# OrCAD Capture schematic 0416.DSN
size D
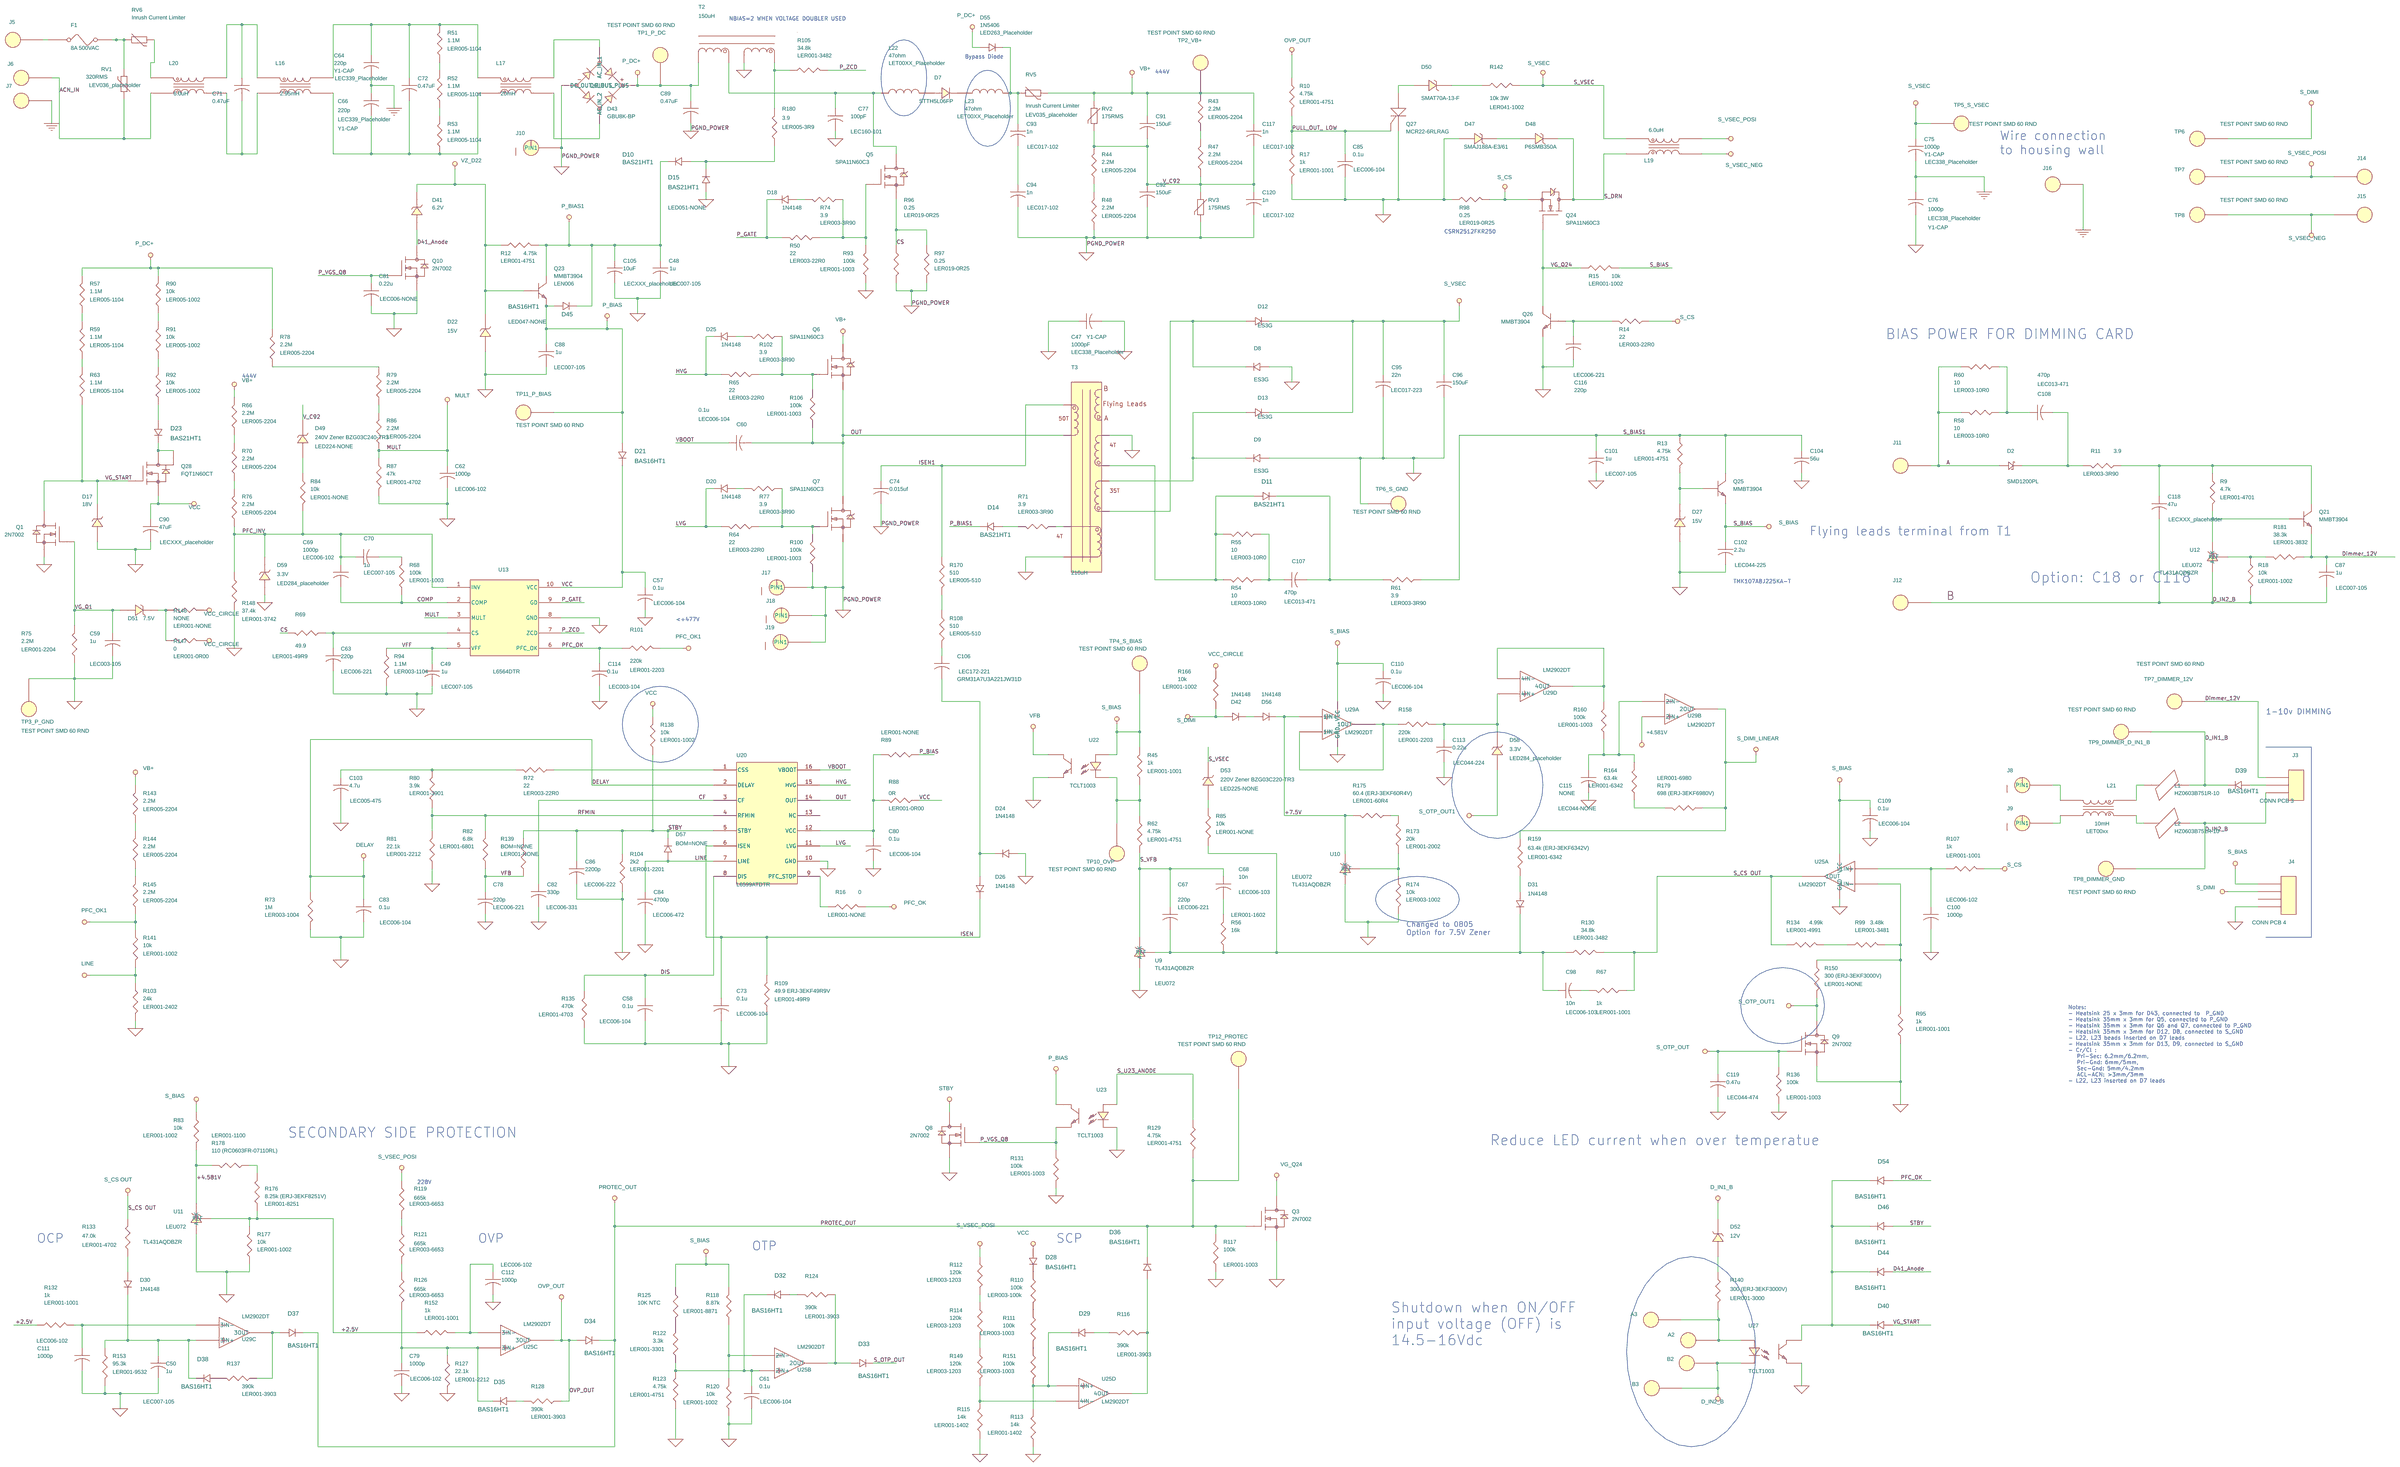
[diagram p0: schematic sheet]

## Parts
A2  TEST POINT SMD 107 RND  [TP-45RD25]
A3  TEST POINT SMD 107 RND  [TP-45RD25]
B2  TEST POINT SMD 107 RND  [TP-45RD25]
B3  TEST POINT SMD 107 RND  [TP-45RD25]
C47  1000pF  [crad-13x4x9p5mm]
C48  1u  [c0805w]
C49  1u  [c0805]
C50  1u  [c0805]
C57  0.1u  [c0603]
C58  0.1u  [c0603w]
C59  1u  [c0603w]
C60  0.1u  [c0603w]
C61  0.1u  [c0603W]
C62  1000p  [c0603W]
C63  220p  [c0603W]
C64  220p  [crad-13x4x9p5mm]
C66  220p  [crad-13x4x9p5mm]
C67  220p  [c0603W]
C68  10n  [c0603W]
C69  1000p  [c0603]
C70  1u  [c0805]
C71  0.47uF  [cap-b32922-9x18mm]
C72  0.47uF  [cap-b32922-9x18mm]
C73  0.1u  [c0603w]
C74  0.015uf  [cap-b32672-18x7x12p5mm]
C75  1000p  [crad-13x4x9p5mm]
C76  1000p  [crad-13x4x9p5mm]
C77  100pF  [c0805]
C78  220p  [c0603w]
C79  1000p  [c0603w]
C80  0.1u  [c0603w]
C81  0.22u  [c0603w]
C82  330p  [c0603w]
C83  0.1u  [c0603w]
C84  4700p  [c0603w]
C85  0.1u  [c0603w]
C86  2200p  [c0603]
C87  1u  [c0805w]
C88  1u  [c0805w]
C89  0.47uF  [cap-ecwf-20p5x13p5-17p5]
C90  47uF  [crad-6p3odx11l]
C91  150uF  [CRAD-18odx25l]
C92  150uF  [CRAD-18odx25l]
C93  1n  [c1206]
C94  1n  [c1206]
C95  22n  [c1206]
C96  150uF  [CRAD-18odx25l]
C98  10n  [c0603W]
C100  1000p  [c0603w]
C101  1u  [c0805w]
C102  2.2u  [c0805]
C103  4.7u  [c1206]
C104  56u  [crad-6p3odx11l]
C105  10uF  [crad-6p3odx11l]
C106  GRM31A7U3A221JW31D  [c1206]
C107  470p  [c0805w]
C108  470p  [c0805w]
C109  0.1u  [c0603W]
C110  0.1u  [c0603W]
C111  1000p  [c0603W]
C112  1000p  [c0603W]
C113  0.22u  [c0805w]
C114  0.1u  [c0603]
C115  NONE  [c0805w]
C116  220p  [c0603w]
C117  1n  [c1206]
C118  47u  [crad-6p3odx11l]
C119  0.47u  [c0805w]
C120  1n  [c1206]
D2  SMD1200PL  [DIO-SOD123]
D7  STTH5L06FP  [DIO-STTH5L06FP]
D8  ES3G  [dio-smc]
D9  ES3G  [dio-smc]
D10  BAS21HT1  [SOD323w]
D11  BAS21HT1  [SOD323w]
D12  ES3G  [dio-smc]
D13  ES3G  [dio-smc]
D14  BAS21HT1  [SOD323w]
D15  BAS21HT1  [SOD323w]
D17  18V  [SOD123]
D18  1N4148  [SOD323]
D20  1N4148  [SOD323w]
D21  BAS16HT1  [SOD323w]
D22  15V  [SOD323w]
D23  BAS21HT1  [SOD323w]
D24  1N4148  [SOD323w]
D25  1N4148  [SOD323w]
D26  1N4148  [SOD323w]
D27  15V  [SOD323]
D28  BAS16HT1  [SOD323w]
D29  BAS16HT1  [SOD323w]
D30  1N4148  [SOD323w]
D31  1N4148  [SOD323]
D32  BAS16HT1  [SOD323w]
D33  BAS16HT1  [SOD323w]
D34  BAS16HT1  [SOD323]
D35  BAS16HT1  [SOD323w]
D36  BAS16HT1  [SOD323w]
D37  BAS16HT1  [SOD323]
D38  BAS16HT1  [SOD323]
D39  BAS16HT1  [SOD323w]
D40  BAS16HT1  [SOD323w]
D41  6.2V  [SOD123]
D42  1N4148  [SOD323w]
D43  GBU8K-BP  [bridge-GBU8X]
D44  BAS16HT1  [SOD323w]
D45  BAS16HT1  [SOD323w]
D46  BAS16HT1  [SOD323w]
D47  SMAJ188A-E3/61  [dio-sma]
D48  P6SMB350A  [dio-smb]
D49  240V Zener BZG03C240-TR3  [dio-smb]
D50  SMAT70A-13-F  [dio-sma]
D51  7.5V  [SOD123]
D52  12V  [SOD323w]
D53  220V Zener BZG03C220-TR3  [dio-smb]
D54  BAS16HT1  [SOD323w]
D55  1N5406  [DIO-DO-201AD]
D56  1N4148  [SOD323w]
D57  BOM=NONE  [SOD323w]
D58  3.3V  [SOD123]
D59  3.3V  [SOD123]
F1  8A 500VAC  [FUSE-0477-V_5A]
J3  CONN PCB 3  [conn3-100]
J4  CONN PCB 4  [conn4-100]
J5  TEST POINT SMD 107 RND  [tp-107rd87]
J6  TEST POINT SMD 107 RND  [tp-107rd87]
J7  TEST POINT SMD 107 RND  [tp-107rd87]
J8  22_AWG  [TP-107RD87]
J9  22_AWG  [TP-107RD87]
J10  18_AWG  [TP-95ob75pth]
J11  TEST POINT SMD 30 RND  [tp-45rd25]
J12  TEST POINT SMD 30 RND  [tp-45rd25]
J14  TEST POINT SMD 107 RND  [tp-107rd87]
J15  TEST POINT SMD 107 RND  [tp-107rd87]
J16  TEST POINT SMD 107 RND  [tp-107rd87]
J17  18_AWG  [TP-95ob75pth]
J18  18_AWG  [TP-95ob75pth]
J19  18_AWG  [TP-95ob75pth]
L1  HZ0603B751R-10  [fb0603w]
L2  HZ0603B751R-10  [fb0603w]
L16  2.95mH  [IND-LET0121-21p3x13p5]
L17  20mH  [IND-LET0120-29x15]
L19  6.0uH  [ind-let0163]
L20  6.0uH  [ind-lc9]
L21  10mH  [ind-ee8-3p4m1]
L22  47ohm  [f0805]
L23  47ohm  [f0805]
Q1  2N7002  [sot23_3-12]
Q3  2N7002  [sot23_3-12]
Q5  SPA11N60C3  [to220-3]
Q6  SPA11N60C3  [to220-3]
Q7  SPA11N60C3  [to220-3]
Q8  2N7002  [sot23_3-12]
Q9  2N7002  [sot23_3-12]
Q10  2N7002  [sot23_3-12]
Q21  MMBT3904  [SOT23_1-32]
Q23  MMBT3904  [SOT23_1-32]
Q24  SPA11N60C3  [to220-3]
Q25  MMBT3904  [SOT23_1-32]
Q26  MMBT3904  [SOT23_1-32]
Q27  MCR22-6RLRAG  [TO-92-KGA]
Q28  FQT1N60CT  [sot223-4]
R9  4.7k  [r0603]
R10  4.75k  [r0603w]
R11  3.9  [r0805w]
R12  4.75k  [r0603w]
R13  4.75k  [r0603]
R14  22  [r0805w]
R15  10k  [r0603w]
R16  0  [r0603w]
R17  1k  [r0603w]
R18  10k  [r0603w]
R43  2.2M  [r1206]
R44  2.2M  [r1206]
R45  1k  [r0603w]
R47  2.2M  [r1206]
R48  2.2M  [r1206]
R50  22  [r0805]
R51  1.1M  [r1206]
R52  1.1M  [r1206]
R53  1.1M  [r1206]
R54  10  [r0805w]
R55  10  [r0805w]
R56  16k  [r0603w]
R57  1.1M  [r1206]
R58  10  [r0805w]
R59  1.1M  [r1206]
R60  10  [r0805w]
R61  3.9  [r0805w]
R62  4.75k  [r0603w]
R63  1.1M  [r1206]
R64  22  [r0805w]
R65  22  [r0805w]
R66  2.2M  [r1206]
R67  1k  [r0603w]
R68  100k  [r0603]
R69  49.9  [r0603]
R70  2.2M  [r1206]
R71  3.9  [r0805w]
R72  22  [r0805w]
R73  1M  [r0805w]
R74  3.9  [r0805]
R75  2.2M  [r0603w]
R76  2.2M  [r1206]
R77  3.9  [r0805w]
R78  2.2M  [r1206]
R79  2.2M  [r1206]
R80  3.9k  [r0603w]
R81  22.1k  [r0603w]
R82  6.8k  [r0603w]
R83  10k  [r0603]
R84  10k  [r0603w]
R85  10k  [r0603]
R86  2.2M  [r1206]
R87  47k  [r0603]
R88  0R  [r0603]
R89  0  [r0603]
R90  10k  [r1206]
R91  10k  [r1206]
R92  10k  [r1206]
R93  100k  [r0603]
R94  1.1M  [r0805]
R95  1k  [r0603w]
R96  0.25  [r2512]
R97  0.25  [r2512]
R98  0.25  [r2512]
R99  3.48k  [r0603]
R100  100k  [r0603w]
R101  220k  [r0603]
R102  3.9  [r0805w]
R103  24k  [r0603w]
R104  2k2  [r0603w]
R105  34.8k  [r0603w]
R106  100k  [r0603w]
R107  1k  [r0603w]
R108  510  [r1206]
R109  49.9 ERJ-3EKF49R9V  [r0603w]
R110  100k  [r0805w]
R111  100k  [r0805w]
R112  120k  [r0805w]
R113  14k  [r0603w]
R114  120k  [r0805w]
R115  14k  [r0603]
R116  390k  [r0603]
R117  100k  [r0603w]
R118  8.87k  [r0603]
R119  665k  [r0805w]
R120  10k  [r0603]
R121  665k  [r0805w]
R122  3.3k  [r0603]
R123  4.75k  [r0603w]
R124  390k  [r0603w]
R125  10K NTC  [r0603]
R126  665k  [r0805w]
R127  22.1k  [r0603w]
R128  390k  [r0603w]
R129  4.75k  [r0603w]
R130  34.8k  [r0603w]
R131  100k  [r0603w]
R132  1k  [r0603]
R133  47.0k  [r0603w]
R134  4.99k  [r0603]
R135  470k  [r0603w]
R136  100k  [r0603w]
R137  390k  [r0603]
R138  10k  [r0603]
R139  BOM=NONE  [r0603w]
R140  300 (ERJ-3EKF3000V)  [r0603]
R141  10k  [r0603w]
R142  10k 3W  [rax-erg-3w-h]
R143  2.2M  [r1206]
R144  2.2M  [r1206]
R145  2.2M  [r1206]
R146  NONE  [r0603w]
R147  0  [r0603w]
R148  37.4k  [r0603w]
R149  120k  [r0805w]
R150  300 (ERJ-3EKF3000V)  [r0603w]
R151  100k  [r0805w]
R152  1k  [r0603w]
R153  95.3k  [r0603]
R158  220k  [r0603w]
R159  63.4k (ERJ-3EKF6342V)  [r0603]
R160  100k  [r0603w]
R164  63.4k  [r0603w]
R166  10k  [r0603w]
R170  510  [r1206]
R173  20k  [r0603w]
R174  10k  [r0805w]
R175  60.4 (ERJ-3EKF60R4V)  [r0603w]
R176  8.25k (ERJ-3EKF8251V)  [r0603w]
R177  10k  [r0603w]
R178  110 (RC0603FR-07110RL)  [r0603w]
R179  698 (ERJ-3EKF6980V)  [r0603w]
R180  3.9  [r1206]
R181  38.3k  [r0603w]
RV1  320RMS  [var-s22k320]
RV2  175RMS  [var-7mm_TVR_S07]
RV3  175RMS  [var-7mm_TVR_S07]
RV5  Inrush Current Limiter  [var-7p5-b57238s]
RV6  Inrush Current Limiter  [var-7p5-b57238s]
T2  150uH  [xfmr-pq32-25_LEX0048_key4-C]
T3  210uH  [XFMR-TXFA-12PIN-c]
TP1_P_DC  TEST POINT SMD 60 RND  [tps-60rd]
TP2_VB+  TEST POINT SMD 60 RND  [tps-60rd]
TP3_P_GND  TEST POINT SMD 60 RND  [tps-60rd]
TP4_S_BIAS  TEST POINT SMD 60 RND  [tps-60rd]
TP5_S_VSEC  TEST POINT SMD 60 RND  [tps-60rd]
TP6  TEST POINT SMD 60 RND  [tps-60rd]
TP6_S_GND  TEST POINT SMD 60 RND  [tps-60rd]
TP7  TEST POINT SMD 60 RND  [tps-60rd]
TP7_DIMMER_12V  TEST POINT SMD 60 RND  [tps-60rd]
TP8  TEST POINT SMD 60 RND  [tps-60rd]
TP8_DIMMER_GND  TEST POINT SMD 60 RND  [tps-60rd]
TP9_DIMMER_D_IN1_B  TEST POINT SMD 60 RND  [tps-60rd]
TP10_OVP  TEST POINT SMD 60 RND  [tps-60rd]
TP11_P_BIAS  TEST POINT SMD 60 RND  [tps-60rd]
TP12_PROTEC  TEST POINT SMD 60 RND  [tps-60rd]
U9  TL431AQDBZR  [SOT23_1-32]
U10  TL431AQDBZR  [SOT23_1-32]
U11  TL431AQDBZR  [SOT23_1-32]
U12  TL431AQDBZR  [SOT23_1-32]
U13  L6564DTR  [sso-10]
U20  L6599ATDTR  [so-16]
U22  TCLT1003  [opto-sop-4l]
U23  TCLT1003  [opto-sop-4l]
U25  LM2902DT  [so-14]  (sections A,B,C,D)
U27  TCLT1003  [opto-sop-4l]
U29  LM2902DT  [so-14]  (sections A,B,C,D)

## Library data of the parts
A2 A3 B2 B3 J5-J7 J14-J16 = TEST_POINT_SMD_107_RND
C47 = LEC039_Y_1000PF_10MM: LLF Part Number: LEC338_Placeholder; TYPE: Y1-CAP
C48-C50 C70 C87 C88 C101 = LEC007_0805_50V: LLF Part Number: LEC007-105
C57 C58 C60 C61 C73 C80 C83 C85 C109 C110 = LEC006_0603_50V: LLF Part Number: LEC006-104
C59 = LEC006_0603_50V: LLF Part Number: LEC003-105
C62 C69 C79 C100 C111 C112 = LEC006_0603_50V: LLF Part Number: LEC006-102
C63 C67 C78 C116 = LEC006_0603_50V: LLF Part Number: LEC006-221
C64 C66 = LEC040_Y_4700PF_10MM: LLF Part Number: LEC339_Placeholder; TYPE: Y1-CAP
C68 C98 = LEC006_0603_50V: LLF Part Number: LEC006-103
C71 C72 = LEC256_FILM_0.47uF_310V
C74 = LEC330_FILM_0.015uF_1.6KVDC_Rad
C75 C76 = LEC040_Y_4700PF_10MM: LLF Part Number: LEC338_Placeholder; TYPE: Y1-CAP
C77 = LEC160_NPO_0805_1000V: LLF Part Number: LEC160-101
C81 = LEC006_0603_50V: LLF Part Number: LEC006-NONE
C82 = LEC006_0603_50V: LLF Part Number: LEC006-331
C84 = LEC006_0603_50V: LLF Part Number: LEC006-472
C86 = LEC006_0603_50V: LLF Part Number: LEC006-222
C89 = LEC255_FILM_0.47uF_630V
C90 C105 C118 = LEC121_CAP_AL_56UF_35V: LLF Part Number: LECXXX_placeholder
C91 C92 C96 = LEC249_AL_150UF_250V_18odx25
C93 C94 C117 C120 = LEC017_1206_500V: LLF Part Number: LEC017-102
C95 = LEC017_1206_500V: LLF Part Number: LEC017-223
C102 = LEC044_0805_25V: LLF Part Number: LEC044-225
C103 = LEC005_1206_16V: LLF Part Number: LEC005-475
C104 = LEC121_CAP_AL_56UF_35V
C106 = LEC172_X7R_1206_1000V: LLF Part Number: LEC172-221
C107 C108 = LEC013_0805_200V: LLF Part Number: LEC013-471
C113 = LEC044_0805_25V: LLF Part Number: LEC044-224
C114 = LEC003_0603_16V: LLF Part Number: LEC003-104
C115 = LEC044_0805_25V: LLF Part Number: LEC044-NONE
C119 = LEC044_0805_25V: LLF Part Number: LEC044-474
D2 = LED166_S_200V_1A_SOD123
D7 = LED181_600V_5V_UF_TO220
D8 D9 D12 D13 = LED066_400V_3A_ES3G_SMC
D10 D11 D14 D23 = LED051_BAS21HT1_SOD323
D15 = LED051_BAS21HT1_SOD323: LLF Part Number: LED051-NONE
D17 = LED184_Z_18V_500mW_SOD123
D18 D20 D24-D26 D30 D31 D42 D56 D57 = LED002_1N4148_SOD323
D21 D28 D29 D32-D40 D44 D46 D54 = LED047_BAS16HT1_SOD323
D22 D27 = LED022_Z_15V_SOD323
D41 = LED190_Z_6.2V_500mW_SOD123
D43 = LED182_BRIDGE_800V_8A_GBU8K
D45 = LED047_BAS16HT1_SOD323: LLF Part Number: LED047-NONE
D47 = LED187_TVS_188V_300W_SMA
D48 = LED188_TVS_350V_600W_SMB
D49 = LED188_TVS_350V_600W_SMB: LLF Part Number: LED224-NONE
D50 = LED183_TVS_70V_400W_SMA
D51 = LED185_Z_7.5V_500mW_SOD123
D52 = LED012_Z_12V_SOD323
D53 = LED188_TVS_350V_600W_SMB: LLF Part Number: LED225-NONE
D55 = LED128_200V_3A_DO-201AD: ALT_SYMBOLS: DIO-DO-201AD-V; LLF Part Number: LED263_Placeholder
D58 D59 = LED185_Z_7.5V_500mW_SOD123: LLF Part Number: LED284_placeholder
F1 = LEF034_8A_500V_0477_TH
J3 = CONN_PCB_3
J4 = CONN_PCB_4
J8 J9 = 22_AWG
J10 J17-J19 = 18_AWG
J11 J12 = TEST_POINT_SMD_30_RND
L1 L2 = LET0011_FERRITE_0603_200MA
L16 = LET0121_CM_2.95mH_21.3x13.5mm
L17 = LET0120_CM_20mH_29x15mm
L19 = LET0163_CM_LC9-752
L20 = LET0081_CM_LC9-671
L21 = LET0029_CM_1.0MH_EE8-3P4M1-0-00: LLF Part Number: LET00xx
L22 L23 = LET0030_IND_SMT_BK2125HS470-T: LLF Part Number: LET00XX_Placeholder
Q1 Q3 Q8-Q10 = LEN008_FET_N_60V_2N7002_SOT23
Q5-Q7 Q24 = LEN128_FET_N_650V_11A_TO220
Q21 Q25 Q26 = LEN006_NPN_40V_MMBT3904_SOT23
Q23 = LEN006_NPN_40V_MMBT3904_SOT23: LLF Part Number: LEN006
Q27 = LEN132_THYRIS_400V_1.5A_TO-92
Q28 = LEN183_FET_SOT223
R9 = LER001_0603_1: LLF Part Number: LER001-4701
R10 R12 R13 R62 R123 R129 = LER001_0603_1: LLF Part Number: LER001-4751
R11 R61 R71 R74 R77 R102 = LER003_0805_1: LLF Part Number: LER003-3R90
R14 R50 R64 R65 R72 = LER003_0805_1: LLF Part Number: LER003-22R0
R15 R18 R83 R120 R138 R141 R166 R177 = LER001_0603_1: LLF Part Number: LER001-1002
R16 R84 R85 R89 R139 R146 R150 = LER001_0603_1: LLF Part Number: LER001-NONE
R17 R45 R67 R95 R107 R132 R152 = LER001_0603_1: LLF Part Number: LER001-1001
R43 R44 R47 R48 R66 R70 R76 R78 R79 R86 R143-R145 = LER005_1206_1: LLF Part Number: LER005-2204
R51-R53 R57 R59 R63 = LER005_1206_1: LLF Part Number: LER005-1104
R54 R55 R58 R60 = LER003_0805_1: LLF Part Number: LER003-10R0
R56 = LER001_0603_1: LLF Part Number: LER001-1602
R68 R93 R100 R106 R117 R131 R136 R160 = LER001_0603_1: LLF Part Number: LER001-1003
R69 R109 = LER001_0603_1: LLF Part Number: LER001-49R9
R73 = LER003_0805_1: LLF Part Number: LER003-1004
R75 = LER001_0603_1: LLF Part Number: LER001-2204
R80 = LER001_0603_1: LLF Part Number: LER001-3901
R81 R127 = LER001_0603_1: LLF Part Number: LER001-2212
R82 = LER001_0603_1: LLF Part Number: LER001-6801
R87 R133 = LER001_0603_1: LLF Part Number: LER001-4702
R88 R147 = LER001_0603_1: LLF Part Number: LER001-0R00
R90-R92 = LER005_1206_1: LLF Part Number: LER005-1002
R94 = LER003_0805_1: LLF Part Number: LER003-1104
R96-R98 = LER019_2512_1: LLF Part Number: LER019-0R25
R99 = LER001_0603_1: LLF Part Number: LER001-3481
R101 R158 = LER001_0603_1: LLF Part Number: LER001-2203
R103 = LER001_0603_1: LLF Part Number: LER001-2402
R104 = LER001_0603_1: LLF Part Number: LER001-2201
R105 R130 = LER001_0603_1: LLF Part Number: LER001-3482
R108 R170 = LER005_1206_1: LLF Part Number: LER005-510
R110 = LER003_0805_1: LLF Part Number: LER003-100k
R111 R151 = LER003_0805_1: LLF Part Number: LER003-1003
R112 R114 R149 = LER003_0805_1: LLF Part Number: LER003-1203
R113 R115 = LER001_0603_1: LLF Part Number: LER001-1402
R116 R124 R128 R137 = LER001_0603_1: LLF Part Number: LER001-3903
R118 = LER001_0603_1: LLF Part Number: LER001-8871
R119 R121 R126 = LER003_0805_1: LLF Part Number: LER003-6653
R122 = LER001_0603_1: LLF Part Number: LER001-3301
R125 = LER024_THERMISTOR_10K_0603
R134 = LER001_0603_1: LLF Part Number: LER001-4991
R135 = LER001_0603_1: LLF Part Number: LER001-4703
R140 = LER001_0603_1: LLF Part Number: LER001-3000
R142 = LER041_3W_AX_TH_5: LLF Part Number: LER041-1002
R148 = LER001_0603_1: LLF Part Number: LER001-3742
R153 = LER001_0603_1: LLF Part Number: LER001-9532
R159 R164 = LER001_0603_1: LLF Part Number: LER001-6342
R173 = LER001_0603_1: LLF Part Number: LER001-2002
R174 = LER003_0805_1: LLF Part Number: LER003-1002
R175 = LER001_0603_1: LLF Part Number: LER001-60R4
R176 = LER001_0603_1: LLF Part Number: LER001-8251
R178 = LER001_0603_1: LLF Part Number: LER001-1100
R179 = LER001_0603_1: LLF Part Number: LER001-6980
R180 = LER005_1206_1: LLF Part Number: LER005-3R9
R181 = LER001_0603_1: LLF Part Number: LER001-3832
RV1 = LEV026_14MM_S14K320E2_320RMS: LLF Part Number: LEV036_placeholder
RV2 RV3 = LEV028_7MM_TVR07271_175RMS
RV5 = LEV035_b572238S_7p5mm: LLF Part Number: LEV035_placeholder
RV6 = LEV035_b572238S_7p5mm
T2 = LEX0048_XFRM_PQ3225_300uH: ALT_SYMBOLS: XFMR-PQ32-25_lex0048_key4
T3 = LEX0065_XFRM_ETD-34-H-12P
TP1_P_DC TP2_VB+ TP3_P_GND TP4_S_BIAS TP5_S_VSEC TP6 TP6_S_GND TP7 TP7_DIMMER_12V TP8 TP8_DIMMER_GND TP9_DIMMER_D_IN1_B TP10_OVP TP11_P_BIAS TP12_PROTEC = TEST_POINT_SMD_60_RND
U9-U12 = LEU094_ZTL431AFTA_SOT23: LLF Part Number: LEU072
U13 = LEU078_L6564
U20 = LEU168_L6599ATDTR_SO16
U22 U23 U27 = LEU169_TCLT1003_SOP-4L
U25 U29 = LEU172_LM2902DT_SO14

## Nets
+2.5V: R132.2 R152.2 R176.2 R177.1 U11.2(REF)
+4.581V: R83.2 R178.1 U11.3(K) U29.5(2IN+)
+7.5V: D56.K(2) R175.1 U10.3(K) U29.3(1IN+)
GND_SIGNAL: C47.2 C50.2 C61.2 C76.2 C79.2 C85.2 C95.2 C96.2 C100.2 C101.2 C102.2 C104.2 C109.2 C110.2 C111.2 C112.2 C113.2 C115.2 C116.2 C119.2 D8.A(1) D9.A(1) D27.A(ANODE) D47.A(1) J4.4 Q3.2(SOURCE) Q9.2(SOURCE) Q26.2(E) Q27.K R17.1 R95.2 R98.1 R113.2 R115.2 R117.2 R120.2 R123.2 R127.2 R136.2 R153.2 R174.1 R177.2 T3.6 TP6_S_GND.1 U9.1(A) U10.1(A) U11.1(A) U23.2 U25.11(GND) U29.11(GND)
PGND_SIGNAL: C47.1 C48.2 C49.2 C57.2 C58.2 C59.2 C62.2 C63.2 C73.2 C74.2 C77.2 C78.2 C80.2 C81.2 C82.2 C83.2 C84.2 C86.2 C88.2 C89.2 C90.2 C92.2 C94.2 C103.2 C105.2 C114.2 C120.2 D15.A(1) D17.A(ANODE) D22.A(ANODE) D24.A(1) D43.4(DC_OUT_MINUS) D59.A(ANODE) J10.1(PIN1) J17.1(PIN1) J18.1(PIN1) J19.1(PIN1) Q1.2(SOURCE) Q7.3(S) Q8.2(SOURCE) Q10.2(SOURCE) R48.1 R73.1 R75.2 R81.2 R87.2 R93.2 R94.1 R96.2 R97.2 R100.2 R103.2 R104.2 R109.2 R131.1 R135.2 R148.2 RV3.2 T2.2 T3.12 TP3_P_GND.1 U13.8(GND) U20.10(GND) U22.3 U27.3
VCC: C57.1 C90.1 D21.K(2) Q28.3(SOURCE) R88.2 R138.1 U13.10(VCC)
A: D2.A(1) J11.1 R58.1 R60.1
ACN_IN: J6.1 L20.3 RV1.1
CF: C82.1 U20.3(CF)
COMP: C69.2 R68.1 U13.2(COMP)
CS: Q5.3(S) R69.1 R96.1 R97.1
D41_Anode: D41.A(ANODE) D44.A(1) Q10.3(DRAIN)
D_IN1_B: D39.K(2) D52.K(CATHODE) L1.2 TP9_DIMMER_D_IN1_B.1
D_IN2_B: B2.1 B3.1 C87.2 C118.2 J3.3 J12.1 L2.2 R18.1 TP8_DIMMER_GND.1 U12.1(A) U27.2
DELAY: C83.1 R73.2 U20.2(DELAY)
Dimmer_12V: C87.1 J3.1 Q21.2(E) R181.2 TP7_DIMMER_12V.1
DIS: C58.1 R135.1 U20.8(DIS)
HVG: D25.K(2) R65.1 U20.15(HVG)
ISEN: C73.1 D26.K(2) R109.1 U20.6(ISEN)
ISEN1: C74.1 R170.1 T3.7
LINE: C84.1 D57.A(1) R103.1 R141.2 U20.7(LINE)
LVG: D20.K(2) R64.1 U20.11(LVG)
MULT: C62.1 R86.1 R87.1 U13.3(MULT)
OUT: C60.2 Q6.3(S) Q7.2(D) R106.2 T3.9 U20.14(OUT)
OVP_OUT: D34.A(1) R10.2 R128.2 U25.8(3OUT)
P_BIAS: C88.1 D21.A(1) D45.A(1) Q23.2(E) R89.2 R146.2 TP11_P_BIAS.1 U23.4
P_BIAS1: C48.1 C105.1 D10.K(2) D14.K(2) D45.K(2) Q23.1(C) R12.1 R147.2
P_DC+: C89.1 D43.1(DC_OUT_PLUS) D55.A(1) R57.2 R78.2 R90.2 T2.10 TP1_P_DC.1
P_EGND2: C64.2 C66.1 J7.1
P_GATE: D18.K(2) R50.1 U13.9(GD)
P_VGS_Q8: C81.1 Q8.1(GATE) Q10.1(GATE) R131.2 U23.3
P_ZCD: R105.2 U13.7(ZCD)
PFC_INV: C69.1 C70.1 D59.K(CATHODE) R76.1 R84.2 R148.1 U13.1(INV)
PFC_OK: C114.1 D54.A(1) R16.1 R101.1 U13.6(PFC_OK)
PFC_OK1: R101.2 R141.1 R145.1
PROTEC_OUT: D34.K(2) D36.K(2) D37.K(2) Q3.1(GATE) R117.1 R129.1 TP12_PROTEC.1
PULL_OUT_ LOW: C85.1 Q27.G R10.1 R17.2
RFMIN: R80.2 R81.1 R82.1 U20.4(RFMIN)
S_BIAS: C102.1 C109.1 C110.1 J4.1 Q25.2(E) R15.1 R45.2 R83.1 R118.1 R125.1 R166.1 TP4_S_BIAS.1 U22.1 U25.4(VCC) U29.4(VCC)
S_BIAS1: C101.1 C104.1 Q25.1(C) R13.2 R61.2
S_CS: Q24.3(S) R14.2 R98.2 R107.1
S_CS OUT: R67.1 R130.1 R133.1 R134.2 U25.1(1OUT)
S_DIMI: D42.A(1) J4.2 R166.2 TP6.1
S_DIMI_LINEAR: R159.1 R179.2 U29.7(2OUT)
S_DRN: D28.A(1) D48.K(2) L19.1 Q24.2(D)
S_EGND: C75.2 C76.1 J16.1
S_OTP_OUT: C119.1 D33.K(2) Q9.1(GATE) R136.1
S_OTP_OUT1: D58.A(ANODE) Q9.3(DRAIN) R150.2
S_U23_ANODE: R129.2 U23.1
S_VFB: C67.1 C68.1 R62.1 U9.3(K)
S_VSEC: C75.1 C95.1 C96.1 D12.K(2) D13.K(2) D53.K(2) L19.2 R142.2 TP5_S_VSEC.1
S_VSEC_NEG: J15.1 L19.4 TP8.1
S_VSEC_POSI: J14.1 L19.3 R112.2 R119.2 TP7.1
STBY: C86.1 D46.A(1) D57.K(2) Q8.3(DRAIN) R104.1 R138.2 R139.1 U20.5(STBY)
V_C92: C91.2 C92.1 C117.2 C120.1 D49.K(2) R44.2 R47.1 RV2.2 RV3.1
VB+: C91.1 C117.1 Q6.2(D) R43.2 R66.2 R143.2 RV2.1 RV5.2 TP2_VB+.1
VBOOT: C60.1 U20.16(VBOOT)
VFB: C78.1 R82.2 R139.2 U22.4
VFF: C49.1 R94.2 U13.5(VFF)
VG_Q1: C59.1 D51.A(ANODE) Q1.1(GATE) R75.1
VG_Q24: Q3.3(DRAIN) Q24.1(G) Q26.1(C) R15.2
VG_START: D17.K(CATHODE) D40.A(1) Q1.3(DRAIN) Q28.1(GATE) R63.1
Vz_D22: D22.K(CATHODE) D41.K(CATHODE) Q23.3(B) R12.2
N10685235: C67.2 C98.1 D31.K(2) R56.1 R85.2 R130.2 U9.2(REF)
N10791701: D43.3(AC_IN_2) L17.4
N11619138: D11.A(1) R54.1 R55.1 T3.5
N12455128: C118.1 Q21.1(C) R9.2 R11.1
N12455191: Q21.3(B) R9.1 U12.3(K)
N12479252: C66.2 C72.2 L16.6 L17.1 R53.1
N12482492: D43.2(AC_IN_1) L17.3
N12483638: C64.1 C72.1 L16.4 L17.2 R51.2
N12486998: R91.1 R92.2
N12492728: C77.1 L22.1 Q5.2(D) T2.7
N12498460: C63.1 R69.2 U13.4(CS)
N12508817: C70.2 R68.2
N12511276: Q5.1(G) R50.2 R74.2 R93.1
N12528990: D18.A(1) R74.1
N12530234: D51.K(CATHODE) R146.1 R147.1
N12548888: C108.2 D2.K(2) R11.2
N12549930: D27.K(CATHODE) Q25.3(B) R13.1
N12552720: Q7.1(G) R64.2 R77.2 R100.1
N12552824: D20.A(1) R77.1
N12553598: Q6.1(G) R65.2 R102.2 R106.1
N12553690: D25.A(1) R102.1
N12560183: D8.K(2) D12.A(1) T3.1
N12560208: D9.K(2) D13.A(1) T3.3
N12563637: C106.1 R108.2
N12564955: R115.1 R149.1 U25.13(4IN-)
N12565313: D29.K(2) R113.1 R151.1 U25.12(4IN+)
N12566314: D36.A(1) R116.2 U25.14(4OUT)
N12566402: D29.A(1) R116.1
N12568198: C61.1 D32.K(2) R122.2 R123.1 U25.5(2IN+)
N12568286: R118.2 R120.1 U25.6(2IN-)
N12568438: D33.A(1) R124.2 U25.7(2OUT)
N12568446: D32.A(1) R124.1
N12572856: C79.1 D35.K(2) R126.1 R127.1 U25.10(3IN+)
N12577697: C80.1 R88.1 R89.1 U20.12(VCC)
N12578837: R72.2 U20.1(CSS)
N12578926: C103.1 R72.1 R80.1
N12580845: R45.1 R62.2 TP10_OVP.1 U22.2
N12588270: D37.A(1) R137.2 U29.8(3OUT)
N12589414: C111.1 R132.1 U29.9(3IN-)
N12589934: C50.1 D30.K(2) D38.K(2) R153.1 U29.10(3IN+)
N12590488: R99.2 R134.1
N12595548: R16.2 U20.9(PFC_STOP)
N12630039: C116.1 Q26.3(B) R14.1
N12638686: C107.2 D11.K(2) R61.1
N12638764: C107.1 R54.2 R55.2
N12639429: C108.1 R58.2 R60.2
N12643014: F1.2 RV1.2 RV6.1
N12692273: C106.2 D24.K(2) D26.A(1)
N12699371: R95.1 R99.1 R150.1 U25.2(1IN-)
N12700568: C100.1 R107.2 U25.3(1IN+)
N12707197: C112.1 R152.1 U25.9(3IN-)
N12730169: D30.A(1) R133.2
N12742487: D50.K(2) R142.1
N12743434: D50.A(1) Q27.A
N12747847: D47.K(2) D48.A(1)
N12805428: R158.2 U29.1(1OUT) U29.2(1IN-)
N12808606: D31.A(1) R159.2
N12811049: C113.1 D58.K(CATHODE) R158.1 U29.12(4IN+)
N12832400: R160.1 U29.13(4IN-) U29.14(4OUT)
N12835772: C115.1 R160.2 R164.1 U29.6(2IN-)
N12891714: R108.1 R170.2
N12894362: C68.2 R56.2
N12899357: R173.2 R174.2 U10.2(REF)
N12902064: R173.1 R175.2
N12904550: R176.1 R178.2
N12907390: R164.2 R179.1
N12914336: J8.1(PIN1) L21.3
N12914343: J9.1(PIN1) L21.2
N12914350: L1.1 L21.4
N12914357: L2.1 L21.1
N12914556: D39.A(1) J3.2
N12925506: D49.A(1) R84.1
N12926206: D53.A(1) R85.1
N12934444: R78.1 R79.2
N12960089: D35.A(1) R128.1
N12964640: A2.1 A3.1 R140.2 U27.1
N12966775: D40.K(2) D44.K(2) D46.K(2) D54.K(2) U27.4
N12982559: D52.A(ANODE) R140.1
N13002970: R105.1 R180.2 T2.1
N13004286: D10.A(1) D15.K(2) R180.1
N13021904: C93.1 D55.K(2) L23.2 RV5.1
N13035527: R70.1 R76.2
N13035915: R144.1 R145.2
N13036788: R59.1 R63.2
N13038410: R79.1 R86.2
N13066955: D42.K(2) D56.A(1)
N13100840: D14.A(1) R71.1
N13102481: R71.2 T3.11
N13181221: C98.2 R67.2
N13188239: C93.2 C94.1
N13223633: D23.A(1) R92.1
N13223645: D23.K(2) Q28.2(DRAIN) Q28.4(DRAIN2)
N13277573: R18.2 R181.1 U12.2(REF)
N13334640: R66.1 R70.2
N13334657: R143.1 R144.2
N13340249: R121.1 R126.2
N13340264: R119.1 R121.2
N13340388: R112.1 R114.2
N13340403: R114.1 R149.2
N13342691: R57.1 R59.2
N13342715: R90.1 R91.2
N13353739: R51.1 R52.2
N13353758: R52.1 R53.2
N13369345: R44.1 R48.2
N13369879: R43.1 R47.2
N13413629: C71.2 L16.1 L20.4
N13413663: L20.1 RV6.2
N13459573: C71.1 L16.3 L20.2
N13520918: F1.1 J5.1
N13529580: D38.A(1) R137.1
N13529582: D7.A(ANODE) L22.2
N13529584: D7.K(CATHODE) L23.1
N13529585: D28.K(2) R110.2
N13529586: R110.1 R111.2
N13529587: R122.1 R125.2
N13529590: R111.1 R151.2

Not connected (* = marked no-connect by the designer): J4 3; U20 13(NC)

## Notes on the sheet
- NBIAS=2 WHEN VOLTAGE DOUBLER USED
- Bypass Diode
- 444V
- Wire connection
  to housing wall
- CSRN2512FKR250
- BIAS POWER FOR DIMMING CARD
- 444V
- Flying leads terminal from T1
- TMK107ABJ225KA-T
- Option: C18 or C118
- <+477V
- 1-10v DIMMING
- Changed to 0805
  Option for 7.5V Zener
- Notes:
  - Heatsink 25 x 3mm for D43, connected to  P_GND
  - Heatsink 35mm x 3mm for Q5, connected to P_GND
  - Heatsink 35mm x 3mm for Q6 and Q7, connected to P_GND
  - Heatsink 35mm x 3mm for D12, D8, connected to S_GND
  - L22, L23 beads inserted on D7 leads
  - Heatsink 35mm x 3mm for D13, D9, connected to S_GND
  - Cr/Cl :
     Pri-Sec: 6.2mm/6.2mm,
     Pri-Gnd: 6mm/5mm,
     Sec-Gnd: 5mm/4.2mm
     ACL-ACN: >3mm/3mm
  - L22, L23 inserted on D7 leads
- SECONDARY SIDE PROTECTION
- Reduce LED current when over temperatue
- 228V
- OCP
- OVP
- SCP
- OTP
- Shutdown when ON/OFF
  input voltage (OFF) is
  14.5-16Vdc
